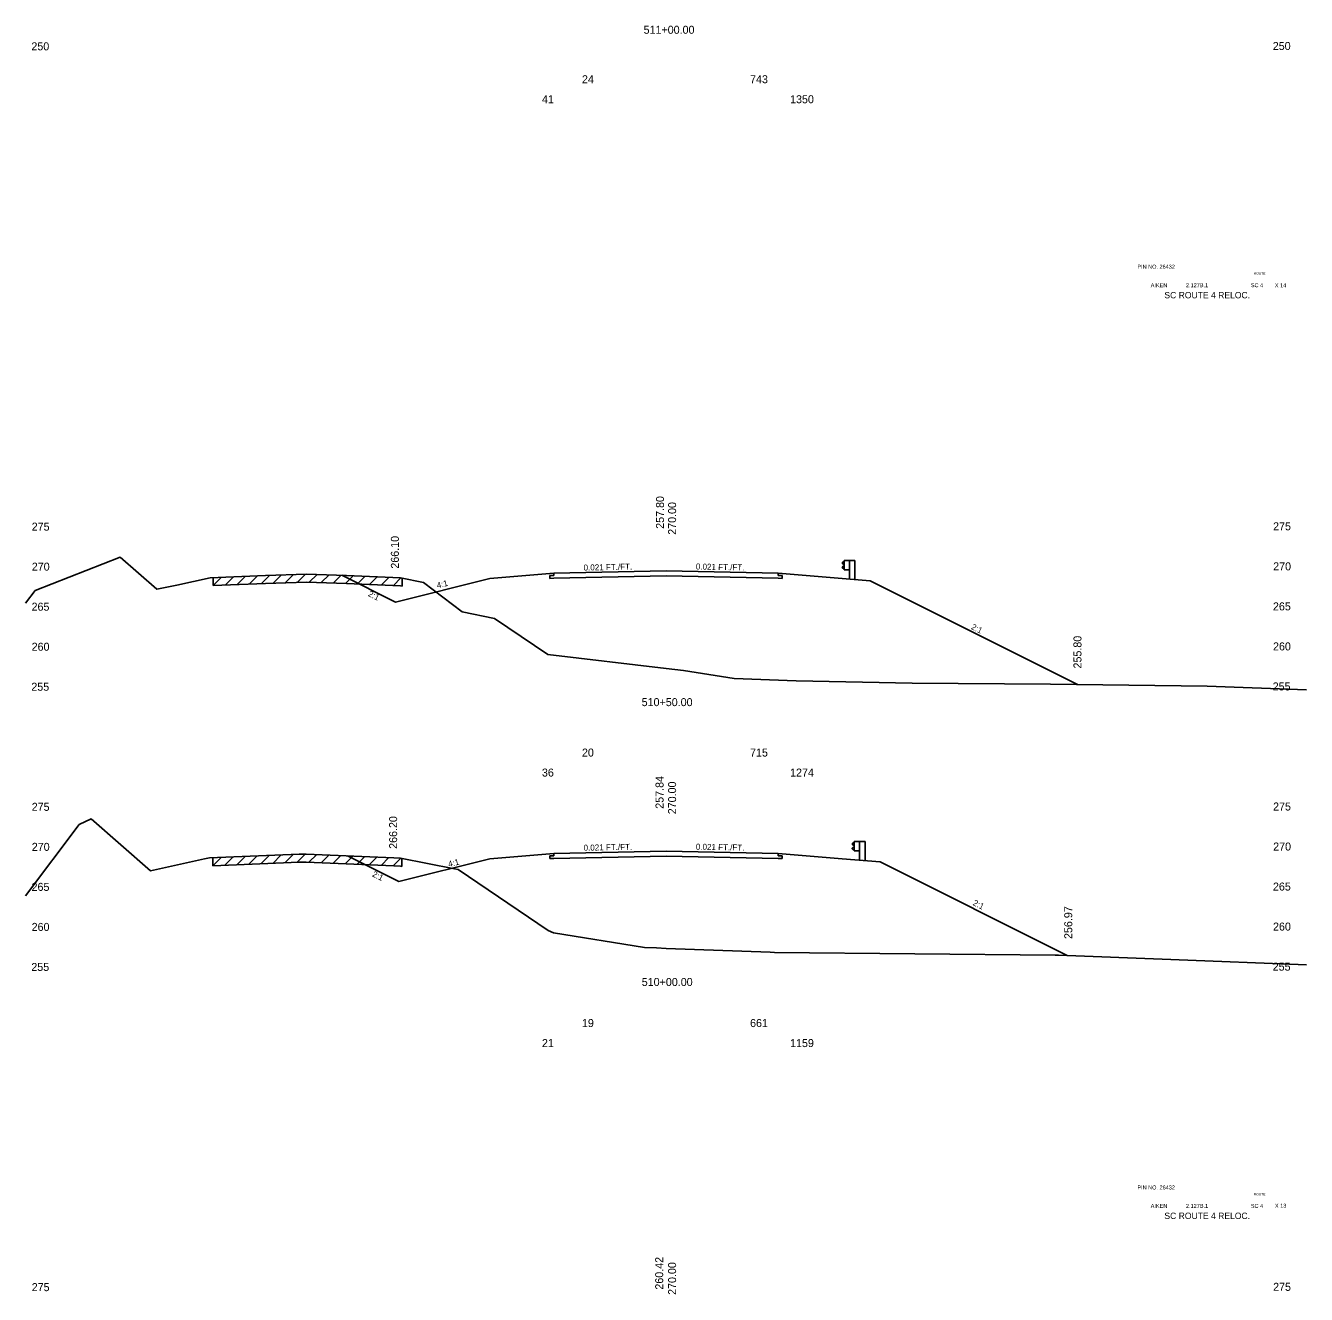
# Model space of a CAD drawing. Extents: x 2967 to 4323, y -3677 to -817.
# Drawn here: x 3188.8 to 3348.8, y -2210.2 to -2051.7 of the extents above; entities that cross this region are included whole.
import ezdxf

# ---------------------------------------------------------------- set-up
doc = ezdxf.new("R2010")
doc.units = 0
for name, color, linetype in [('Level 1', 7, 'Continuous'), ('Level 10', 7, 'Continuous'), ('Level 11', 7, 'Continuous'), ('Level 12', 7, 'Continuous'), ('Level 20', 7, 'Continuous'), ('Level 24', 7, 'Continuous'), ('Level 3', 7, 'Continuous'), ('Level 32', 7, 'Continuous'), ('Level 33', 7, 'Continuous'), ('Level 59', 7, 'Continuous'), ('Level 6', 7, 'Continuous'), ('Level 60', 7, 'Continuous'), ('Level 61', 7, 'Continuous'), ('Level 7', 7, 'Continuous')]:
    doc.layers.add(name, color=color, linetype=linetype)

msp = doc.modelspace()

# ---------------------------------------------------------------- linework, layer by layer
at = {"layer": 'Level 11'}
for p, q in [((3254.76, -2120.43), (3254.26, -2120.44)), ((3254.26, -2120.44), (3254.26, -2120.78)), ((3254.26, -2120.78), (3254.76, -2120.77)), ((3254.76, -2120.13), (3254.76, -2120.43)), ((3282.76, -2120.43), (3282.76, -2120.13)), ((3283.26, -2120.44), (3282.76, -2120.43)), ((3282.76, -2120.77), (3283.26, -2120.78)), ((3283.26, -2120.78), (3283.26, -2120.44)), ((3254.76, -2155.13), (3254.76, -2155.43)), ((3282.76, -2155.43), (3282.76, -2155.13)), ((3254.76, -2155.43), (3254.26, -2155.44)), ((3254.26, -2155.44), (3254.26, -2155.78)), ((3254.26, -2155.78), (3254.76, -2155.77)), ((3283.26, -2155.44), (3282.76, -2155.43)), ((3282.76, -2155.77), (3283.26, -2155.78)), ((3283.26, -2155.78), (3283.26, -2155.44))]:
    msp.add_line(p, q, dxfattribs=at)
at = {"layer": 'Level 12'}
for p, q in [((3268.76, -2120.48), (3254.76, -2120.77)), ((3282.76, -2120.77), (3268.76, -2120.48)), ((3268.76, -2155.48), (3254.76, -2155.77)), ((3282.76, -2155.77), (3268.76, -2155.48))]:
    msp.add_line(p, q, dxfattribs=at)
at = {"layer": 'Level 24'}
for p, q in [((3291.03, -2118.62), (3290.76, -2118.82)), ((3290.76, -2118.82), (3290.76, -2118.87)), ((3290.76, -2118.87), (3291.03, -2119.07)), ((3290.76, -2119.39), (3291.03, -2119.19)), ((3290.76, -2119.44), (3290.76, -2119.39)), ((3291.03, -2119.64), (3290.76, -2119.44)), ((3291.03, -2119.72), (3291.03, -2118.55)), ((3291.03, -2118.55), (3291.7, -2118.55)), ((3291.03, -2119.72), (3291.7, -2119.72)), ((3291.7, -2118.55), (3291.7, -2120.88)), ((3291.7, -2118.55), (3292.36, -2118.55)), ((3292.36, -2118.55), (3292.36, -2120.93)), ((3292.28, -2153.73), (3292.01, -2153.93)), ((3292.01, -2153.93), (3292.01, -2153.98)), ((3292.01, -2153.98), (3292.28, -2154.18)), ((3292.01, -2154.5), (3292.28, -2154.3)), ((3292.01, -2154.55), (3292.01, -2154.5)), ((3292.28, -2154.75), (3292.01, -2154.55)), ((3292.28, -2154.82), (3292.28, -2153.65)), ((3292.28, -2153.65), (3292.95, -2153.65)), ((3292.28, -2154.82), (3292.95, -2154.82)), ((3292.95, -2153.65), (3292.95, -2155.98)), ((3292.95, -2153.65), (3293.62, -2153.65)), ((3293.62, -2153.65), (3293.62, -2156.04))]:
    msp.add_line(p, q, dxfattribs=at)
at = {"layer": 'Level 59'}
for p, q in [((3254.76, -2120.13), (3268.76, -2119.84)), ((3268.76, -2119.84), (3282.76, -2120.13)), ((3254.76, -2155.13), (3268.76, -2154.84)), ((3268.76, -2154.84), (3282.76, -2155.13))]:
    msp.add_line(p, q, dxfattribs=at)
at = {"layer": 'Level 6'}
for p, q in [((3246.76, -2120.8), (3254.76, -2120.13)), ((3282.76, -2120.13), (3290.76, -2120.8)), ((3290.76, -2120.8), (3294.26, -2121.09)), ((3246.76, -2155.8), (3254.76, -2155.13)), ((3282.76, -2155.13), (3290.76, -2155.8)), ((3290.76, -2155.8), (3295.51, -2156.2))]:
    msp.add_line(p, q, dxfattribs=at)
at = {"layer": 'Level 60'}
for p, q in [((3189.94, -2122.31), (3200.55, -2118.12)), ((3200.55, -2118.12), (3205.15, -2122.15)), ((3207.65, -2121.62), (3211.82, -2120.7)), ((3211.82, -2120.7), (3218.74, -2120.42)), ((3218.74, -2120.42), (3223.84, -2120.24)), ((3223.84, -2120.24), (3228.85, -2120.41)), ((3228.85, -2120.41), (3235.6, -2120.71)), ((3235.6, -2120.71), (3238.45, -2121.28)), ((3238.45, -2121.28), (3243.3, -2124.96)), ((3188.76, -2123.88), (3189.94, -2122.31)), ((3205.15, -2122.15), (3207.65, -2121.62)), ((3243.3, -2124.96), (3247.35, -2125.79)), ((3247.35, -2125.79), (3253.99, -2130.28)), ((3253.99, -2130.28), (3268.76, -2132.04)), ((3268.76, -2132.04), (3270.96, -2132.3)), ((3270.96, -2132.3), (3277.29, -2133.3)), ((3277.29, -2133.3), (3285.03, -2133.57)), ((3285.03, -2133.57), (3299.5, -2133.87)), ((3299.5, -2133.87), (3316.78, -2134)), ((3316.78, -2134), (3336.35, -2134.25)), ((3336.35, -2134.25), (3348.76, -2134.72)), ((3188.76, -2160.43), (3195.44, -2151.52)), ((3195.44, -2151.52), (3196.95, -2150.83)), ((3196.95, -2150.83), (3204.35, -2157.3)), ((3204.35, -2157.3), (3211.11, -2155.82)), ((3211.11, -2155.82), (3211.71, -2155.69)), ((3211.71, -2155.69), (3222.93, -2155.25)), ((3222.93, -2155.25), (3223.79, -2155.22)), ((3223.79, -2155.22), (3234.75, -2155.7)), ((3234.75, -2155.7), (3235.61, -2155.73)), ((3235.61, -2155.73), (3242.34, -2157.06)), ((3242.34, -2157.06), (3242.78, -2157.14)), ((3242.78, -2157.14), (3254.05, -2164.77)), ((3254.05, -2164.77), (3254.69, -2165.08)), ((3254.69, -2165.08), (3266.08, -2166.91)), ((3266.08, -2166.91), (3267.57, -2166.95)), ((3267.57, -2166.95), (3268.76, -2167)), ((3268.76, -2167), (3281.77, -2167.49)), ((3281.77, -2167.49), (3282.31, -2167.5)), ((3282.31, -2167.5), (3317.38, -2167.83)), ((3317.38, -2167.83), (3317.78, -2167.83)), ((3317.78, -2167.83), (3331.83, -2168.41)), ((3331.83, -2168.41), (3348.76, -2169.06))]:
    msp.add_line(p, q, dxfattribs=at)
at = {"layer": 'Level 61'}
for p, q in [((3213.24, -2120.64), (3212.2, -2121.68)), ((3212.2, -2120.68), (3212.2, -2121.68)), ((3212.2, -2121.68), (3218.74, -2121.42)), ((3214.74, -2120.58), (3213.7, -2121.62)), ((3216.24, -2120.52), (3215.2, -2121.56)), ((3217.74, -2120.46), (3216.7, -2121.51)), ((3219.24, -2120.41), (3218.2, -2121.45)), ((3218.74, -2121.42), (3223.84, -2121.24)), ((3220.74, -2120.35), (3219.7, -2121.39)), ((3222.24, -2120.3), (3221.2, -2121.34)), ((3223.74, -2120.24), (3222.7, -2121.28)), ((3223.84, -2121.24), (3228.85, -2121.41)), ((3225.17, -2120.29), (3224.2, -2121.25)), ((3226.67, -2120.34), (3225.7, -2121.3)), ((3228.17, -2120.39), (3227.2, -2121.36)), ((3229.66, -2120.45), (3228.7, -2121.41)), ((3228.85, -2121.41), (3235.6, -2121.71)), ((3231.16, -2120.51), (3230.2, -2121.47)), ((3232.66, -2120.58), (3231.7, -2121.54)), ((3234.16, -2120.65), (3233.2, -2121.6)), ((3235.65, -2120.72), (3234.7, -2121.67)), ((3235.78, -2121.75), (3235.78, -2120.75)), ((3235.6, -2121.71), (3235.78, -2121.75)), ((3213.2, -2155.63), (3212.16, -2156.67)), ((3212.16, -2155.67), (3212.16, -2156.67)), ((3212.16, -2156.67), (3222.93, -2156.25)), ((3214.7, -2155.57), (3213.66, -2156.61)), ((3216.2, -2155.51), (3215.16, -2156.55)), ((3217.7, -2155.45), (3216.66, -2156.49)), ((3219.2, -2155.39), (3218.16, -2156.44)), ((3220.7, -2155.33), (3219.66, -2156.38)), ((3222.2, -2155.27), (3221.16, -2156.32)), ((3223.7, -2155.22), (3222.66, -2156.26)), ((3222.93, -2156.25), (3223.79, -2156.22)), ((3223.79, -2156.22), (3234.75, -2156.7)), ((3225.12, -2155.27), (3224.16, -2156.23)), ((3226.62, -2155.34), (3225.66, -2156.3)), ((3228.12, -2155.41), (3227.16, -2156.36)), ((3229.62, -2155.47), (3228.66, -2156.43)), ((3231.12, -2155.54), (3230.16, -2156.5)), ((3232.62, -2155.6), (3231.66, -2156.56)), ((3234.12, -2155.67), (3233.16, -2156.63)), ((3235.62, -2155.73), (3234.66, -2156.69)), ((3234.75, -2156.7), (3235.61, -2156.73)), ((3235.61, -2156.73), (3235.76, -2156.76)), ((3235.76, -2156.76), (3235.76, -2155.76))]:
    msp.add_line(p, q, dxfattribs=at)
at = {"layer": 'Level 7'}
for p, q in [((3228.26, -2120.39), (3234.97, -2123.75)), ((3246.76, -2120.8), (3234.97, -2123.75)), ((3294.26, -2121.09), (3320.16, -2134.04)), ((3228.97, -2155.44), (3235.37, -2158.65)), ((3246.76, -2155.8), (3235.37, -2158.65)), ((3295.51, -2156.2), (3318.87, -2167.88))]:
    msp.add_line(p, q, dxfattribs=at)

# ---------------------------------------------------------------- texts
at = {"layer": 'Level 1'}
for s, p in [('24', (3258.26, -2058.93)), ('743', (3279.26, -2058.93)), ('41', (3253.26, -2061.43)), ('1350', (3284.26, -2061.43)), ('20', (3258.26, -2143.04)), ('715', (3279.26, -2143.04)), ('36', (3253.26, -2145.54)), ('1274', (3284.26, -2145.54)), ('19', (3258.26, -2176.83)), ('661', (3279.26, -2176.83)), ('21', (3253.26, -2179.33)), ('1159', (3284.26, -2179.33))]:
    msp.add_text(s, height=1, dxfattribs=at).set_placement(p)
at = {"layer": 'Level 10'}
for s, p in [('511+00.00', (3265.96, -2052.75)), ('510+50.00', (3265.72, -2136.74)), ('510+00.00', (3265.73, -2171.7))]:
    msp.add_text(s, height=1, dxfattribs=at).set_placement(p)
for s, p in [('257.80', (3268.51, -2114.59)), ('257.84', (3268.45, -2149.56)), ('260.42', (3268.41, -2209.63))]:
    msp.add_text(s, height=1, rotation=90, dxfattribs=at).set_placement(p)
at = {"layer": 'Level 20'}
for s, height, p in [('PIN NO. 26432', 0.5, (3327.65, -2082.1)), ('ROUTE', 0.3, (3342.19, -2082.84)), ('AIKEN', 0.5, (3329.31, -2084.41)), (' 2.127B.1', 0.5, (3333.53, -2084.41)), ('SC 4', 0.5, (3341.82, -2084.41)), ('X 14', 0.5, (3344.82, -2084.42)), ('SC ROUTE 4 RELOC.', 0.8, (3331.02, -2085.8)), ('PIN NO. 26432', 0.5, (3327.65, -2197.12)), ('ROUTE', 0.3, (3342.19, -2197.86)), ('AIKEN', 0.5, (3329.31, -2199.42)), ('SC ROUTE 4 RELOC.', 0.8, (3331.02, -2200.81)), (' 2.127B.1', 0.5, (3333.53, -2199.42)), ('SC 4', 0.5, (3341.82, -2199.42)), ('X 13', 0.5, (3344.83, -2199.4))]:
    msp.add_text(s, height=height, dxfattribs=at).set_placement(p)
at = {"layer": 'Level 3'}
for s, p in [(' 250', (3189.11, -2054.82)), (' 250', (3344.19, -2054.78)), (' 275', (3189.15, -2114.82)), (' 275', (3344.23, -2114.78)), (' 270', (3189.16, -2119.82)), (' 270', (3344.24, -2119.78)), (' 265', (3189.13, -2124.82)), (' 265', (3344.21, -2124.78)), (' 260', (3189.14, -2129.82)), (' 260', (3344.22, -2129.78)), (' 255', (3189.1, -2134.82)), (' 255', (3344.18, -2134.78)), (' 275', (3344.23, -2149.78)), (' 275', (3189.15, -2149.82)), (' 270', (3189.16, -2154.82)), (' 270', (3344.24, -2154.78)), (' 265', (3189.13, -2159.82)), (' 265', (3344.21, -2159.78)), (' 260', (3189.14, -2164.82)), (' 260', (3344.22, -2164.78)), (' 255', (3189.1, -2169.82)), (' 255', (3344.18, -2169.78)), (' 275', (3189.15, -2209.82)), (' 275', (3344.23, -2209.78))]:
    msp.add_text(s, height=1, dxfattribs=at).set_placement(p)
at = {"layer": 'Level 32'}
for s, rotation, p in [('0.021 FT./FT.', 1.1916, (3258.47, -2119.81)), ('0.021 FT./FT.', 358.8084, (3272.48, -2119.67)), ('4:1', 14.0362, (3240.22, -2122.04)), ('2:1', 333.435, (3231.47, -2122.96)), ('2:1', 333.435, (3306.81, -2127.09)), ('0.021 FT./FT.', 1.1916, (3258.47, -2154.81)), ('0.021 FT./FT.', 358.8084, (3272.48, -2154.67)), ('4:1', 14.0362, (3241.64, -2156.86)), ('2:1', 333.435, (3231.98, -2157.97)), ('2:1', 333.435, (3307.02, -2161.56))]:
    msp.add_text(s, height=0.75, rotation=rotation, dxfattribs=at).set_placement(p)
at = {"layer": 'Level 33'}
for s, p in [('266.10', (3235.39, -2119.57)), ('255.80', (3320.66, -2132.04)), ('266.20', (3235.17, -2154.57)), ('256.97', (3319.51, -2165.83))]:
    msp.add_text(s, height=1, rotation=90, dxfattribs=at).set_placement(p)
at = {"layer": 'Level 59'}
for p in [(3270.02, -2115.71), (3270.02, -2150.62), (3270.02, -2210.66)]:
    msp.add_text(' 270.00', height=1, rotation=90, dxfattribs=at).set_placement(p)

doc.saveas('drawing.dxf')
